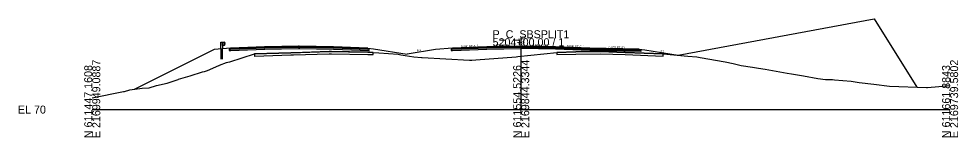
# Model space of a CAD drawing. Extents: x -26 to 1303, y -3010 to 12033.
# Drawn here: x 974.3 to 1302.8, y 3990.3 to 4031.8 of the extents above; entities that cross this region are included whole.
import ezdxf

# ---------------------------------------------------------------- set-up
doc = ezdxf.new("R2010")
doc.units = 0
for name, color, linetype in [('RD_GPK_XS_Cell', 7, 'Continuous'), ('RD_PD_Final_TrvlWay', 7, 'Continuous'), ('RD_Sketch10', 7, 'Continuous'), ('RD_XS_Base', 7, 'Continuous'), ('RD_XS_ExGround', 7, 'Continuous'), ('RD_XS_ExPaveRet', 7, 'Continuous'), ('RD_XS_GR', 7, 'Continuous'), ('RD_XS_Greenside', 7, 'Continuous'), ('RD_XS_Pave', 7, 'Continuous'), ('RD_XS_PaveOvlay_CP', 7, 'Continuous'), ('RD_XS_TieSlope', 7, 'Continuous'), ('RD_XS_TX_Elev_EX', 7, 'Continuous'), ('RD_XS_TX_Elev_PR', 7, 'Continuous'), ('RD_XS_TX_Slope', 7, 'Continuous')]:
    doc.layers.add(name, color=color, linetype=linetype)

msp = doc.modelspace()

# ---------------------------------------------------------------- linework, layer by layer
at = {"layer": 'RD_GPK_XS_Cell'}
for p, q in [((1150, 4000), (1150, 4025)), ((1000, 4000), (1150, 4000)), ((1150, 4000), (1300, 4000))]:
    msp.add_line(p, q, dxfattribs=at)
at = {"layer": 'RD_PD_Final_TrvlWay'}
msp.add_lwpolyline([(1045.5, 4017.66), (1045.5, 4021.26), (1045, 4021.22), (1045, 4017.66)], dxfattribs=at)
at = {"layer": 'RD_Sketch10'}
msp.add_lwpolyline([(1204.92, 4019.05), (1273.45, 4031.83), (1288.34, 4007.86)], dxfattribs=at)
at = {"layer": 'RD_XS_Base'}
for p, q in [((1060.24, 4021.65), (1048.48, 4021.18)), ((1060.39, 4021.66), (1060.24, 4021.65)), ((1072.08, 4021.89), (1060.39, 4021.66)), ((1060.39, 4021.16), (1072.08, 4021.39)), ((1072.39, 4021.9), (1072.08, 4021.89)), ((1072.08, 4021.39), (1072.39, 4021.4)), ((1072.39, 4021.9), (1072.39, 4022.05)), ((1072.39, 4022.05), (1072.39, 4022.05)), ((1072.39, 4022.05), (1072.39, 4022.04)), ((1072.39, 4021.9), (1072.39, 4022.05)), ((1072.39, 4022.05), (1072.39, 4022.05)), ((1072.39, 4022.05), (1072.39, 4022.05)), ((1072.39, 4022.05), (1072.39, 4021.4)), ((1072.39, 4022.04), (1072.39, 4021.4)), ((1072.39, 4021.88), (1072.39, 4021.9)), ((1072.39, 4021.4), (1072.39, 4021.9)), ((1072.39, 4021.9), (1072.39, 4021.9)), ((1072.39, 4021.9), (1072.39, 4021.9)), ((1072.39, 4021.9), (1072.39, 4021.9)), ((1084.39, 4021.66), (1072.39, 4021.9)), ((1072.39, 4021.4), (1072.39, 4021.88)), ((1072.39, 4021.4), (1072.39, 4021.4)), ((1072.39, 4021.4), (1072.39, 4021.4)), ((1072.39, 4021.4), (1084.39, 4021.16)), ((1096.39, 4021.18), (1084.39, 4021.66)), ((1086.39, 4021.58), (1086.39, 4021.58)), ((1138, 4021.66), (1126, 4021.18)), ((1136, 4021.58), (1136, 4021.58)), ((1150, 4021.9), (1138, 4021.66)), ((1138, 4021.16), (1150, 4021.4)), ((1150, 4021.4), (1150, 4022.05)), ((1150, 4022.05), (1150, 4022.05)), ((1150, 4022.05), (1150, 4022.05)), ((1150, 4022.05), (1150, 4021.9)), ((1150, 4021.9), (1150, 4021.9)), ((1150, 4021.9), (1162, 4021.66)), ((1150, 4021.9), (1150, 4021.9)), ((1150, 4021.4), (1150, 4021.9)), ((1150, 4021.9), (1150, 4021.9)), ((1150, 4021.9), (1150, 4021.9)), ((1162, 4021.16), (1150, 4021.4)), ((1150, 4021.4), (1150, 4021.4)), ((1150, 4021.4), (1150, 4021.4)), ((1162, 4021.66), (1162, 4021.66)), ((1162, 4021.66), (1174, 4021.18)), ((1048.39, 4021.18), (1047.89, 4021.16)), ((1047.89, 4021.16), (1047.89, 4021.16)), ((1047.89, 4021.16), (1047.89, 4020.66)), ((1047.89, 4020.66), (1048.39, 4020.68)), ((1047.89, 4020.66), (1047.89, 4020.66)), ((1047.89, 4020.66), (1047.89, 4020.66)), ((1048.39, 4021.18), (1048.39, 4021.18)), ((1048.48, 4021.18), (1048.39, 4021.18)), ((1048.39, 4020.68), (1048.39, 4020.68)), ((1048.39, 4020.68), (1048.48, 4020.68)), ((1048.48, 4020.68), (1060.24, 4021.15)), ((1060.24, 4021.15), (1060.39, 4021.16)), ((1084.39, 4021.16), (1096.89, 4020.66)), ((1086.39, 4021.08), (1086.39, 4021.08)), ((1096.89, 4021.16), (1096.39, 4021.18)), ((1096.39, 4021.18), (1096.39, 4021.18)), ((1096.89, 4020.66), (1096.89, 4021.16)), ((1096.89, 4021.16), (1096.89, 4021.16)), ((1126, 4021.18), (1125.5, 4021.16)), ((1125.5, 4021.16), (1125.5, 4021.16)), ((1125.5, 4021.16), (1125.5, 4020.66)), ((1125.5, 4020.66), (1126, 4020.68)), ((1126, 4021.18), (1126, 4021.18)), ((1126, 4020.68), (1138, 4021.16)), ((1126, 4020.68), (1126, 4020.68)), ((1136, 4021.08), (1136, 4021.08)), ((1174, 4020.68), (1162, 4021.16)), ((1162, 4021.16), (1162, 4021.16)), ((1174, 4021.18), (1174, 4021.18)), ((1174, 4021.18), (1191.3, 4020.83)), ((1191.8, 4020.32), (1174, 4020.68)), ((1174, 4020.68), (1174, 4020.68)), ((1191.3, 4020.83), (1191.3, 4020.83)), ((1191.3, 4020.83), (1191.8, 4020.82)), ((1191.8, 4020.82), (1191.8, 4020.82)), ((1191.8, 4020.82), (1191.8, 4020.32))]:
    msp.add_line(p, q, dxfattribs=at)
at = {"layer": 'RD_XS_ExGround'}
msp.add_lwpolyline([(1000, 4004.14), (1010.88, 4006.29), (1011.23, 4006.36), (1013.12, 4006.89), (1017.46, 4007.48), (1019.9, 4007.68), (1022.47, 4008.39), (1026.2, 4009.31), (1027.58, 4009.76), (1030.01, 4010.5), (1030.18, 4010.61), (1034.26, 4011.81), (1038.61, 4013.18), (1039.25, 4013.37), (1040.28, 4013.75), (1044.21, 4015.42), (1044.35, 4015.48), (1044.4, 4015.5), (1044.5, 4015.54), (1046.99, 4016.51), (1047.4, 4016.62), (1048.09, 4016.71), (1056.71, 4019.49), (1069.46, 4019.9), (1082.88, 4020.33), (1096.4, 4020.09), (1098.25, 4020.05), (1100.22, 4019.84), (1106.98, 4019.37), (1107.93, 4019.22), (1112.48, 4018.5), (1115.13, 4018.29), (1115.38, 4018.27), (1131.96, 4017.31), (1132.77, 4017.28), (1134.18, 4017.39), (1148.22, 4018.5), (1148.82, 4018.57), (1162.52, 4020.04), (1169.09, 4020.18), (1177.69, 4020.33), (1186.41, 4020), (1199.6, 4019.51), (1208.33, 4018.75), (1211.45, 4018.51), (1212.55, 4018.25), (1221.36, 4016.71), (1224.08, 4016.16), (1226.94, 4015.47), (1230.88, 4014.84), (1232.96, 4014.5), (1235.3, 4014.16), (1242.97, 4012.78), (1244.49, 4012.5), (1248.79, 4011.77), (1253.74, 4010.94), (1256.45, 4010.6), (1258.9, 4010.5), (1259.6, 4010.47), (1265.42, 4009.98), (1268.17, 4009.47), (1273.32, 4008.86), (1278.86, 4008.24), (1291.74, 4007.72), (1291.8, 4007.71), (1292.07, 4007.74), (1300, 4008.44)], dxfattribs=at)
at = {"layer": 'RD_XS_ExPaveRet'}
for points in [[(1096.4, 4020.09), (1083.7, 4020.31), (1082.88, 4020.33), (1070.38, 4019.93), (1069.46, 4019.9), (1056.85, 4019.5), (1056.71, 4019.49), (1056.71, 4018.76), (1056.71, 4018.74), (1056.85, 4018.75), (1069.46, 4019.15), (1070.38, 4019.18), (1082.88, 4019.58), (1083.7, 4019.56), (1096.4, 4019.34), (1096.94, 4019.33), (1098.25, 4019.3), (1098.25, 4019.97), (1098.25, 4020.05), (1096.94, 4020.08), (1096.4, 4020.09)], [(1096.4, 4020.09), (1083.7, 4020.31), (1082.88, 4020.33), (1070.38, 4019.93), (1069.46, 4019.9), (1056.85, 4019.5), (1056.71, 4019.49), (1056.71, 4018.76), (1056.71, 4018.74), (1056.85, 4018.75), (1069.46, 4019.15), (1070.38, 4019.18), (1082.88, 4019.58), (1083.7, 4019.56), (1096.4, 4019.34), (1096.94, 4019.33), (1098.25, 4019.3), (1098.25, 4019.97), (1098.25, 4020.05), (1096.94, 4020.08), (1096.4, 4020.09)], [(1186.41, 4020), (1177.69, 4020.33), (1177.69, 4020.33), (1169.09, 4020.18), (1169.09, 4020.18), (1162.52, 4020.04), (1162.52, 4020.04), (1162.52, 4020.04), (1162.52, 4020.04), (1162.52, 4019.29), (1162.52, 4019.29), (1162.52, 4019.29), (1169.09, 4019.43), (1169.09, 4019.43), (1177.69, 4019.58), (1177.69, 4019.58), (1186.41, 4019.25), (1186.41, 4019.25), (1199.6, 4018.76), (1199.6, 4019.51), (1199.6, 4019.51), (1186.41, 4020), (1186.41, 4020)], [(1186.41, 4020), (1177.69, 4020.33), (1169.09, 4020.18), (1162.52, 4020.04), (1162.52, 4019.29), (1169.09, 4019.43), (1177.69, 4019.58), (1186.41, 4019.25), (1199.6, 4018.76), (1199.6, 4019.51), (1186.41, 4020)]]:
    msp.add_lwpolyline(points, dxfattribs=at)
at = {"layer": 'RD_XS_GR'}
for p, q in [((1045, 4021.22), (1045, 4023.66)), ((1045, 4023.66), (1045.25, 4023.66)), ((1045.5, 4021.26), (1045, 4021.22)), ((1045.25, 4023.66), (1045.5, 4023.66)), ((1045.5, 4023.66), (1045.5, 4021.26)), ((1045.5, 4022.49), (1045.5, 4023.66)), ((1045.5, 4023.66), (1046.17, 4023.66)), ((1046.17, 4022.49), (1045.5, 4022.49)), ((1046.17, 4023.66), (1046.17, 4022.49)), ((1046.44, 4023.37), (1046.17, 4023.66)), ((1046.17, 4023.66), (1046.17, 4022.49)), ((1046.17, 4023.08), (1046.44, 4023.37)), ((1046.17, 4023.07), (1046.17, 4023.08)), ((1046.44, 4022.78), (1046.17, 4023.07)), ((1046.17, 4022.49), (1046.44, 4022.78)), ((1046.17, 4022.49), (1046.17, 4022.49)), ((1046.17, 4022.49), (1046.17, 4022.49)), ((1046.44, 4023.37), (1046.44, 4023.37)), ((1046.44, 4022.78), (1046.44, 4022.78))]:
    msp.add_line(p, q, dxfattribs=at)
at = {"layer": 'RD_XS_Greenside'}
for p, q in [((1098.39, 4021.33), (1110.16, 4019.37)), ((1042.69, 4021.04), (1014.63, 4007.01)), ((1120, 4021.01), (1110.16, 4019.37)), ((1193.3, 4020.99), (1204.92, 4019.05))]:
    msp.add_line(p, q, dxfattribs=at)
at = {"layer": 'RD_XS_Pave'}
for p, q in [((1048.48, 4021.5), (1048.39, 4021.49)), ((1048.39, 4021.49), (1048.39, 4021.49)), ((1048.39, 4021.49), (1048.39, 4021.33)), ((1048.48, 4021.34), (1048.39, 4021.33)), ((1048.39, 4021.33), (1048.48, 4021.34)), ((1048.39, 4021.33), (1048.39, 4021.33)), ((1048.39, 4021.33), (1048.39, 4021.18)), ((1048.39, 4021.33), (1048.39, 4021.33)), ((1048.39, 4021.33), (1048.39, 4021.33)), ((1060.24, 4021.97), (1048.48, 4021.5)), ((1060.24, 4021.81), (1048.48, 4021.34)), ((1048.48, 4021.34), (1060.24, 4021.81)), ((1048.48, 4021.18), (1060.24, 4021.65)), ((1060.39, 4021.97), (1060.24, 4021.97)), ((1060.39, 4021.81), (1060.24, 4021.81)), ((1060.24, 4021.81), (1060.39, 4021.81)), ((1060.24, 4021.65), (1060.39, 4021.66)), ((1072.08, 4022.21), (1060.39, 4021.97)), ((1072.08, 4022.05), (1060.39, 4021.81)), ((1060.39, 4021.81), (1072.08, 4022.05)), ((1060.39, 4021.66), (1072.08, 4021.89)), ((1072.39, 4022.21), (1072.08, 4022.21)), ((1072.39, 4022.05), (1072.08, 4022.05)), ((1072.08, 4022.05), (1072.39, 4022.05)), ((1072.08, 4021.89), (1072.39, 4021.9)), ((1084.39, 4021.97), (1072.39, 4022.21)), ((1072.39, 4022.21), (1072.39, 4022.21)), ((1072.39, 4022.21), (1072.39, 4022.21)), ((1072.39, 4021.9), (1072.39, 4022.05)), ((1072.39, 4022.05), (1072.39, 4022.05)), ((1072.39, 4022.05), (1072.39, 4022.05)), ((1072.39, 4022.05), (1072.39, 4021.9)), ((1072.39, 4021.9), (1072.39, 4022.05)), ((1072.39, 4022.05), (1072.39, 4022.05)), ((1072.39, 4022.05), (1072.39, 4022.05)), ((1072.39, 4022.05), (1072.39, 4022.05)), ((1072.39, 4022.05), (1072.39, 4022.05)), ((1072.39, 4022.05), (1084.39, 4021.81)), ((1084.39, 4021.81), (1072.39, 4022.05)), ((1072.39, 4022.05), (1072.39, 4022.05)), ((1072.39, 4022.05), (1072.39, 4022.05)), ((1072.39, 4022.05), (1072.39, 4021.9)), ((1072.39, 4021.9), (1072.39, 4021.9)), ((1072.39, 4021.9), (1072.39, 4021.9)), ((1072.39, 4021.9), (1084.39, 4021.66)), ((1096.39, 4021.49), (1084.39, 4021.97)), ((1084.39, 4021.81), (1096.39, 4021.33)), ((1096.39, 4021.33), (1084.39, 4021.81)), ((1084.39, 4021.66), (1096.39, 4021.18)), ((1086.39, 4021.89), (1086.39, 4021.89)), ((1086.39, 4021.73), (1086.39, 4021.73)), ((1086.39, 4021.73), (1086.39, 4021.73)), ((1086.39, 4021.58), (1086.39, 4021.58)), ((1096.39, 4021.33), (1096.39, 4021.49)), ((1096.39, 4021.49), (1096.39, 4021.49)), ((1096.39, 4021.18), (1096.39, 4021.33)), ((1096.39, 4021.33), (1096.39, 4021.33)), ((1138, 4021.97), (1126, 4021.49)), ((1138, 4021.81), (1126, 4021.33)), ((1126, 4021.33), (1138, 4021.81)), ((1126, 4021.18), (1138, 4021.66)), ((1126, 4021.49), (1126, 4021.49)), ((1126, 4021.49), (1126, 4021.33)), ((1126, 4021.33), (1126, 4021.33)), ((1126, 4021.33), (1126, 4021.18)), ((1136, 4021.89), (1136, 4021.89)), ((1136, 4021.73), (1136, 4021.73)), ((1136, 4021.73), (1136, 4021.73)), ((1136, 4021.58), (1136, 4021.58)), ((1150, 4022.21), (1138, 4021.97)), ((1150, 4022.05), (1138, 4021.81)), ((1138, 4021.81), (1150, 4022.05)), ((1138, 4021.66), (1150, 4021.9)), ((1162, 4021.97), (1150, 4022.21)), ((1150, 4022.21), (1150, 4022.21)), ((1150, 4022.21), (1150, 4022.21)), ((1150, 4021.9), (1150, 4022.05)), ((1150, 4022.05), (1150, 4022.05)), ((1150, 4022.05), (1150, 4022.05)), ((1150, 4022.05), (1150, 4022.05)), ((1150, 4022.05), (1150, 4022.05)), ((1150, 4022.05), (1162, 4021.81)), ((1162, 4021.81), (1150, 4022.05)), ((1150, 4022.05), (1150, 4022.05)), ((1150, 4022.05), (1150, 4022.05)), ((1150, 4022.05), (1150, 4022.05)), ((1150, 4022.05), (1150, 4021.9)), ((1150, 4021.9), (1150, 4021.9)), ((1150, 4021.9), (1150, 4021.9)), ((1150, 4021.9), (1150, 4021.9)), ((1150, 4021.9), (1162, 4021.66)), ((1174, 4021.49), (1162, 4021.97)), ((1162, 4021.97), (1162, 4021.97)), ((1162, 4021.81), (1162, 4021.81)), ((1162, 4021.81), (1174, 4021.33)), ((1174, 4021.33), (1162, 4021.81)), ((1162, 4021.81), (1162, 4021.81)), ((1162, 4021.66), (1162, 4021.66)), ((1162, 4021.66), (1174, 4021.18)), ((1191.3, 4021.15), (1174, 4021.49)), ((1174, 4021.49), (1174, 4021.49)), ((1174, 4021.33), (1174, 4021.33)), ((1174, 4021.33), (1191.3, 4020.99)), ((1191.3, 4020.99), (1174, 4021.33)), ((1174, 4021.33), (1174, 4021.33)), ((1048.39, 4021.18), (1048.39, 4021.18)), ((1048.39, 4021.18), (1048.39, 4021.18)), ((1048.39, 4021.18), (1048.48, 4021.18)), ((1174, 4021.18), (1191.3, 4020.83)), ((1174, 4021.18), (1174, 4021.18)), ((1191.3, 4020.99), (1191.3, 4021.15)), ((1191.3, 4021.15), (1191.3, 4021.15)), ((1191.3, 4020.83), (1191.3, 4020.99)), ((1191.3, 4020.99), (1191.3, 4020.99))]:
    msp.add_line(p, q, dxfattribs=at)
at = {"layer": 'RD_XS_PaveOvlay_CP'}
for p, q in [((1048.39, 4021.49), (1048.48, 4021.5)), ((1048.48, 4021.5), (1060.39, 4021.97)), ((1060.39, 4021.97), (1072.39, 4022.21)), ((1072.39, 4022.21), (1084.39, 4021.97)), ((1084.39, 4021.97), (1096.39, 4021.49)), ((1138, 4021.97), (1126, 4021.49)), ((1136, 4021.89), (1136, 4021.89)), ((1150, 4022.21), (1138, 4021.97)), ((1162, 4021.97), (1150, 4022.21)), ((1150, 4022.21), (1150, 4022.21)), ((1150, 4022.21), (1150, 4022.21)), ((1174, 4021.49), (1162, 4021.97)), ((1162, 4021.97), (1162, 4021.97)), ((1191.3, 4021.15), (1174, 4021.49)), ((1174, 4021.49), (1174, 4021.49))]:
    msp.add_line(p, q, dxfattribs=at)
at = {"layer": 'RD_XS_TieSlope'}
for p, q in [((1048.39, 4021.49), (1042.69, 4021.04)), ((1096.39, 4021.49), (1098.39, 4021.33)), ((1126, 4021.49), (1120, 4021.01)), ((1191.3, 4021.15), (1193.3, 4020.99))]:
    msp.add_line(p, q, dxfattribs=at)

# ---------------------------------------------------------------- texts
at = {"layer": 'RD_GPK_XS_Cell'}
for s, p in [('P_C_SBSPLIT1', (1140, 4025)), ('5204+00.00 / 1', (1140, 4022.2)), ('EL 70', (974, 3998.6))]:
    msp.add_text(s, height=2.8, dxfattribs=at).set_placement(p)
for s, p in [('N 611447.1608', (1000, 3990)), ('E 2169949.0887', (1002.8, 3990)), ('N 611554.5226', (1150, 3990)), ('E 2169844.3344', (1152.8, 3990)), ('N 611661.8843', (1300, 3990)), ('E 2169739.5802', (1302.8, 3990))]:
    msp.add_text(s, height=2.8, rotation=90, dxfattribs=at).set_placement(p)
at = {"layer": 'RD_XS_TX_Elev_EX'}
msp.add_text('88.68', height=0.6, rotation=90, dxfattribs=at).set_placement((1149.63, 4022.82))
at = {"layer": 'RD_XS_TX_Elev_PR'}
msp.add_text('92.21', height=1, rotation=90, dxfattribs=at).set_placement((1151.2, 4022.4))
at = {"layer": 'RD_XS_TX_Slope'}
for s, rotation, p in [('6:1', 9.4642, (1113.57, 4020.35)), ('0.040 FT./FT.', 2.2906, (1128.93, 4021.71)), ('0.020 FT./FT.', 1.1458, (1140.27, 4022.18)), ('0.020 FT./FT.', 358.8542, (1153.94, 4022.23)), ('0.040 FT./FT.', 357.7094, (1165.94, 4021.91)), ('0.020 FT./FT.', 358.8542, (1180.59, 4021.46)), ('6:1', 350.5377, (1198.6, 4020.16))]:
    msp.add_text(s, height=0.75, rotation=rotation, dxfattribs=at).set_placement(p)

doc.saveas('drawing.dxf')
